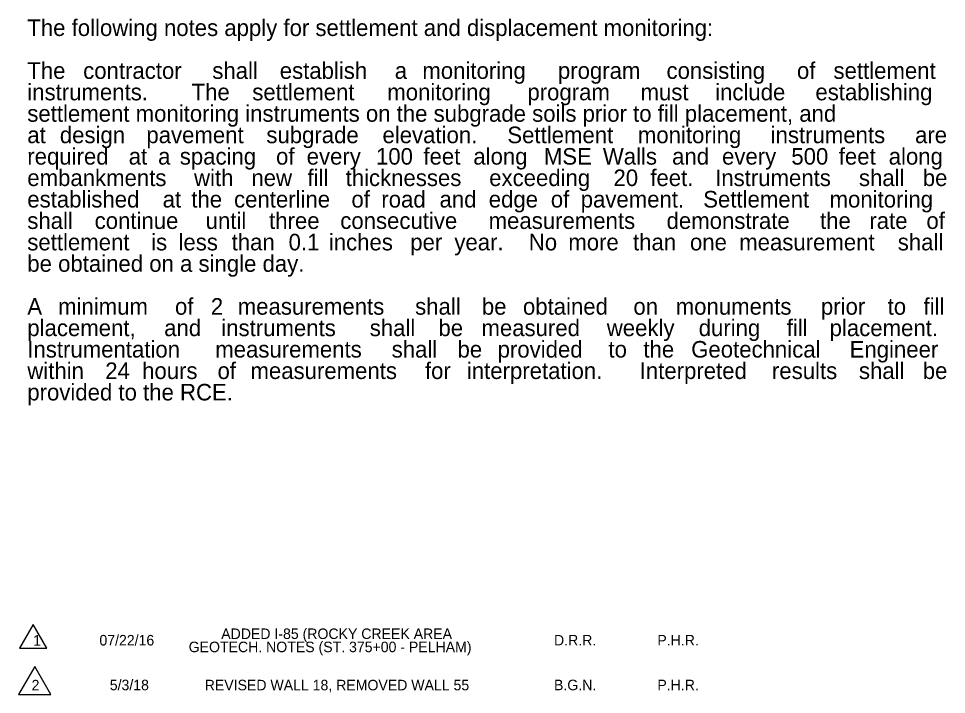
# Model space of a CAD drawing. Extents: x 4804 to 5434, y 4929 to 5221.
# Drawn here: x 5017.2 to 5094.8, y 5018.4 to 5074.9 of the extents above; entities that cross this region are included whole.
import ezdxf

# ---------------------------------------------------------------- set-up
doc = ezdxf.new("R2010")
doc.units = 0
for name, color, linetype in [('Default', 7, 'Continuous'), ('RD_SHT_TX', 7, 'Continuous'), ('RD_TX_RoadID', 7, 'Continuous')]:
    doc.layers.add(name, color=color, linetype=linetype)

msp = doc.modelspace()

# ---------------------------------------------------------------- linework, layer by layer
at = {"layer": 'Default'}
for points in [[(5017.276, 5022.259), (5019.577, 5022.259), (5018.427, 5024.252)], [(5017.21, 5018.405), (5019.907, 5018.405), (5018.558, 5020.74)]]:
    msp.add_lwpolyline(points, close=True, dxfattribs=at)

# ---------------------------------------------------------------- texts
for s, p in [('1', (5018.427, 5022.483)), ('2', (5018.303, 5018.743))]:
    msp.add_text(s, height=0.88, dxfattribs=at).set_placement(p)
at = {"layer": 'RD_SHT_TX'}
for s, height, p in [('ADDED I-85 (ROCKY CREEK AREA', 0.87999, (5034.15, 5023.038)), ('07/22/16', 0.88, (5023.969, 5022.497)), ('D.R.R.', 0.88, (5061.963, 5022.497)), ('P.H.R.', 0.88, (5070.6, 5022.497)), ('GEOTECH. NOTES (ST. 375+00 - PELHAM)', 0.87999, (5031.429, 5021.937)), ('5/3/18', 0.88, (5024.834, 5018.757)), ('REVISED WALL 18, REMOVED WALL 55', 0.87999, (5032.769, 5018.748)), ('B.G.N.', 0.88, (5061.963, 5018.757)), ('P.H.R.', 0.88, (5070.6, 5018.757))]:
    msp.add_text(s, height=height, dxfattribs=at).set_placement(p)
at = {"layer": 'RD_TX_RoadID'}
for s, p in [('The following notes apply for settlement and displacement monitoring:', (5017.942, 5073.439)), ('The ', (5017.942, 5069.855)), ('contractor ', (5022.611, 5069.855)), ('shall ', (5033.405, 5069.855)), ('establish ', (5039.041, 5069.855)), ('monitoring ', (5050.959, 5069.855)), ('consisting ', (5071.365, 5069.855)), ('of ', (5082.267, 5069.855)), ('settlement ', (5085.322, 5069.855)), ('a ', (5048.654, 5069.855)), ('program ', (5062.289, 5069.855)), ('instruments. ', (5017.942, 5068.063)), (' The ', (5031.159, 5068.063)), ('settlement ', (5036.746, 5068.063)), ('monitoring ', (5048.028, 5068.063)), ('program ', (5059.739, 5068.063)), ('must ', (5069.196, 5068.063)), ('include ', (5075.428, 5068.063)), ('establishing ', (5083.81, 5068.063)), ('settlement monitoring instruments on the subgrade soils prior to fill placement, and ', (5017.942, 5066.271)), ('at ', (5017.942, 5064.48)), ('design ', (5020.661, 5064.48)), ('pavement ', (5027.894, 5064.48)), ('subgrade ', (5037.922, 5064.48)), ('elevation. ', (5047.628, 5064.48)), (' Settlement ', (5057.548, 5064.48)), ('monitoring ', (5068.971, 5064.48)), ('instruments ', (5080.071, 5064.48)), ('are ', (5092.139, 5064.48)), ('required ', (5017.942, 5062.688)), ('spacing ', (5030.685, 5062.688)), ('of ', (5038.73, 5062.688)), ('feet ', (5051.046, 5062.688)), ('along ', (5055.22, 5062.688)), ('Walls ', (5066.045, 5062.688)), ('and ', (5071.832, 5062.688)), ('feet ', (5085.761, 5062.688)), ('along ', (5089.936, 5062.688)), ('at ', (5026.417, 5062.688)), ('a ', (5028.873, 5062.688)), ('every ', (5041.293, 5062.688)), ('100 ', (5047.083, 5062.688)), ('MSE ', (5061.115, 5062.688)), ('every ', (5076.008, 5062.688)), ('500 ', (5081.798, 5062.688)), ('embankments ', (5017.942, 5060.896)), ('with ', (5031.876, 5060.896)), ('new ', (5036.672, 5060.896)), ('fill ', (5041.362, 5060.896)), ('thicknesses ', (5044.546, 5060.896)), ('exceeding ', (5056.546, 5060.896)), ('20 ', (5066.933, 5060.896)), ('feet. ', (5070.012, 5060.896)), (' Instruments ', (5074.916, 5060.896)), ('shall ', (5087.45, 5060.896)), ('be ', (5092.785, 5060.896)), ('established ', (5017.942, 5059.104)), ('at ', (5029.255, 5059.104)), ('the ', (5031.648, 5059.104)), ('centerline ', (5035.222, 5059.104)), ('of ', (5045.031, 5059.104)), ('road ', (5047.53, 5059.104)), ('and ', (5052.395, 5059.104)), ('edge ', (5056.508, 5059.104)), ('of ', (5061.695, 5059.104)), ('pavement. ', (5064.194, 5059.104)), ('Settlement ', (5074.434, 5059.104)), ('monitoring ', (5084.994, 5059.104)), ('shall ', (5017.942, 5057.312)), ('continue ', (5023.569, 5057.312)), ('until ', (5032.848, 5057.312)), ('three ', (5038.151, 5057.312)), ('consecutive ', (5044.1, 5057.312)), ('demonstrate ', (5071.371, 5057.312)), ('the ', (5084.198, 5057.312)), ('of ', (5093.087, 5057.312)), ('measurements ', (5056.499, 5057.312)), ('rate ', (5088.32, 5057.312)), ('settlement ', (5017.942, 5055.52)), ('is ', (5028.29, 5055.52)), ('less ', (5030.58, 5055.52)), ('than ', (5035.02, 5055.52)), ('0.1 ', (5039.78, 5055.52)), ('inches ', (5043.145, 5055.52)), ('per ', (5049.949, 5055.52)), ('year. ', (5053.636, 5055.52)), ('  No ', (5058.828, 5055.52)), ('more ', (5063.159, 5055.52)), ('than ', (5068.566, 5055.52)), ('one ', (5073.326, 5055.52)), ('measurement ', (5077.442, 5055.52)), ('shall ', (5090.695, 5055.52)), ('be obtained on a single day.  ', (5017.942, 5053.729)), ('A ', (5017.942, 5050.145)), ('minimum ', (5020.512, 5050.145)), ('of ', (5030.283, 5050.145)), ('2 ', (5033.282, 5050.145)), ('measurements ', (5035.53, 5050.145)), ('shall ', (5050.355, 5050.145)), ('be ', (5055.935, 5050.145)), ('obtained ', (5059.366, 5050.145)), ('on ', (5068.598, 5050.145)), ('monuments ', (5072.135, 5050.145)), ('prior ', (5084.27, 5050.145)), ('to ', (5089.848, 5050.145)), ('fill ', (5092.847, 5050.145)), ('placement, ', (5017.942, 5048.353)), ('and ', (5029.382, 5048.353)), ('instruments ', (5034.157, 5048.353)), ('shall ', (5046.563, 5048.353)), ('be ', (5052.306, 5048.353)), ('measured ', (5055.9, 5048.353)), ('weekly ', (5066.375, 5048.353)), ('during ', (5074.055, 5048.353)), ('fill ', (5081.408, 5048.353)), ('placement. ', (5085, 5048.353)), ('Instrumentation ', (5017.942, 5046.561)), ('measurements ', (5033.65, 5046.561)), ('shall ', (5048.397, 5046.561)), ('be ', (5053.899, 5046.561)), ('provided ', (5057.251, 5046.561)), ('to ', (5066.513, 5046.561)), ('the ', (5069.434, 5046.561)), ('Geotechnical ', (5073.43, 5046.561)), ('Engineer ', (5086.67, 5046.561)), ('within ', (5017.942, 5044.769)), ('24 ', (5024.457, 5044.769)), ('hours ', (5027.537, 5044.769)), ('of ', (5033.839, 5044.769)), ('measurements ', (5036.594, 5044.769)), ('for ', (5051.175, 5044.769)), ('interpretation. ', (5054.682, 5044.769)), (' Interpreted ', (5068.612, 5044.769)), ('results ', (5080.179, 5044.769)), ('shall ', (5087.449, 5044.769)), ('be ', (5092.785, 5044.769)), ('provided to the RCE.  ', (5017.942, 5042.978))]:
    msp.add_text(s, height=1.3845, dxfattribs=at).set_placement(p)

doc.saveas('drawing.dxf')
